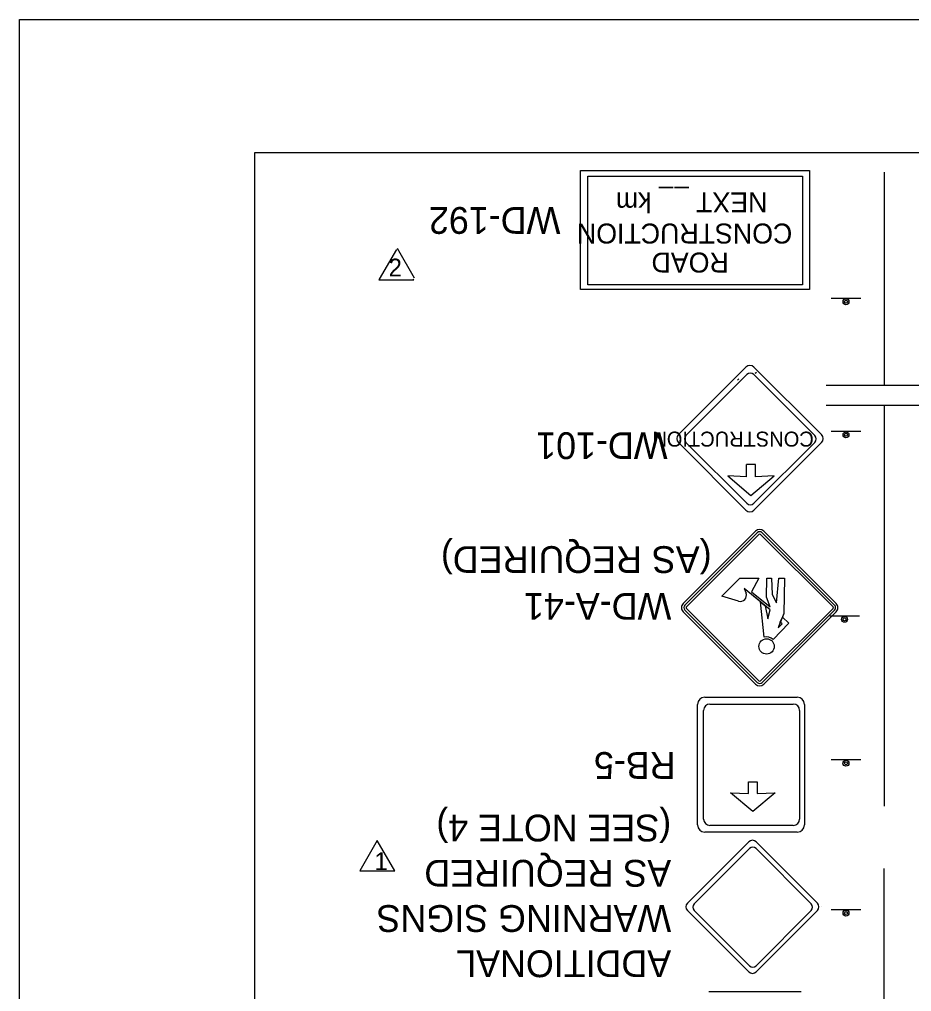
# Model space of a CAD drawing. Extents: x 1372 to 1588, y 125 to 404.
# Drawn here: x 1372.1 to 1444.6, y 325 to 404 of the extents above; entities that cross this region are included whole.
import ezdxf

# ---------------------------------------------------------------- set-up
doc = ezdxf.new("R2010")
doc.units = 0
for name, color, linetype in [('Level 1', 7, 'Continuous'), ('Level 10', 7, 'Continuous'), ('Level 2', 7, 'Continuous'), ('Level 44', 7, 'Continuous'), ('Level 60', 7, 'Continuous'), ('Level 63', 7, 'Continuous')]:
    doc.layers.add(name, color=color, linetype=linetype)

msp = doc.modelspace()

# ---------------------------------------------------------------- linework, layer by layer
at = {"layer": 'Level 1'}
for p, q in [((1431.885, 362.391), (1425.997, 356.51)), ((1432.015, 362.26), (1426.128, 356.379)), ((1432.146, 362.129), (1426.259, 356.248)), ((1438.172, 356.244), (1432.287, 362.129)), ((1438.303, 356.375), (1432.419, 362.26)), ((1438.434, 356.507), (1432.55, 362.391)), ((1425.997, 355.845), (1431.881, 349.961)), ((1426.128, 355.976), (1432.011, 350.092)), ((1426.258, 356.107), (1432.142, 350.222)), ((1432.284, 350.222), (1438.172, 356.103)), ((1432.415, 350.091), (1438.303, 355.973)), ((1432.546, 349.96), (1438.433, 355.842)), ((1432.488, 352.538), (1432.503, 352.538))]:
    msp.add_line(p, q, dxfattribs=at)
for points in [[(1430.489, 356.695), (1429.138, 357.098), (1430.599, 358.574), (1432.137, 358.574), (1431.561, 357.461), (1433.053, 356.239), (1432.761, 357.018), (1432.799, 358.574), (1433.165, 358.574), (1433.232, 357.245), (1433.591, 356.566), (1433.779, 358.574), (1434.229, 358.574), (1434.168, 355.691), (1433.705, 354.533), (1434.031, 354.867)], [(1430.489, 356.695), (1429.138, 357.098), (1430.599, 358.574), (1432.137, 358.574), (1431.561, 357.461), (1433.053, 356.239), (1432.761, 357.018), (1432.799, 358.574), (1433.165, 358.574), (1433.232, 357.245), (1433.591, 356.566), (1433.779, 358.574), (1434.229, 358.574), (1434.168, 355.691), (1433.705, 354.533), (1434.031, 354.867)], [(1430.489, 356.695), (1429.138, 357.098), (1430.599, 358.574), (1432.137, 358.574), (1431.561, 357.461), (1433.053, 356.239), (1432.761, 357.018), (1432.799, 358.574), (1433.165, 358.574), (1433.232, 357.245), (1433.591, 356.566)], [(1433.591, 356.566), (1433.779, 358.574), (1434.229, 358.574), (1434.168, 355.691), (1434.057, 355.413), (1434.591, 354.908), (1433.308, 353.583)], [(1432.572, 353.772), (1432.274, 356.642), (1432.657, 356.326), (1432.875, 355.256), (1433.052, 356.001), (1430.956, 357.731), (1431.101, 357.357)], [(1432.572, 353.772), (1432.274, 356.642), (1432.657, 356.326), (1432.875, 355.256), (1433.052, 356.001), (1430.956, 357.731), (1431.101, 357.357)], [(1432.572, 353.772), (1432.274, 356.643), (1430.956, 357.731), (1431.101, 357.357)], [(1434.031, 354.867), (1433.888, 354.988), (1434.058, 355.412), (1434.591, 354.908), (1433.308, 353.583)], [(1434.031, 354.867), (1433.888, 354.988), (1434.058, 355.412), (1434.591, 354.908), (1433.308, 353.583)]]:
    msp.add_lwpolyline(points, dxfattribs=at)
for points in [[(1432.657, 356.328), (1432.875, 355.256), (1433.052, 356.001)], [(1434.031, 354.867), (1433.887, 354.988), (1433.705, 354.533)], [(1401.132, 337.257), (1399.713, 334.787), (1402.551, 334.787)]]:
    msp.add_lwpolyline(points, close=True, dxfattribs=at)
msp.add_circle((1432.773, 353.023), 0.624, dxfattribs=at)
msp.add_circle((1432.773, 353.023), 0.624, dxfattribs=at)
msp.add_circle((1432.773, 353.023), 0.624, dxfattribs=at)
for centre, radius, start, end in [((1432.217, 362.058), 0.471, 45, 134.96517), ((1432.217, 362.058), 0.285, 45, 134.96517), ((1432.217, 362.058), 0.1, 45, 134.96517), ((1430.633, 357.176), 0.502, 253.38102, 21.09993), ((1430.633, 357.176), 0.502, 253.38102, 21.09993), ((1430.633, 357.176), 0.502, 253.38102, 21.09993), ((1426.329, 356.178), 0.471, 134.96511, 225), ((1426.329, 356.178), 0.285, 134.96511, 225), ((1438.101, 356.174), 0.285, 314.965, 45), ((1438.101, 356.174), 0.471, 314.965, 45), ((1426.329, 356.178), 0.1, 134.96511, 225), ((1438.101, 356.174), 0.1, 314.965, 45), ((1432.773, 353.023), 0.775, 46.3135, 104.9576), ((1432.773, 353.023), 0.775, 46.3135, 104.9576), ((1432.773, 353.023), 0.775, 46.3135, 104.9576), ((1432.214, 350.294), 0.285, 225, 314.96508), ((1432.214, 350.294), 0.1, 225, 314.96508), ((1432.214, 350.294), 0.471, 225, 314.96508)]:
    msp.add_arc(centre, radius, start, end, dxfattribs=at)
at = {"layer": 'Level 10'}
for p, q in [((1442.325, 391.558), (1442.325, 374.244)), ((1442.325, 372.627), (1442.325, 340.053)), ((1442.325, 157.871), (1442.325, 334.977))]:
    msp.add_line(p, q, dxfattribs=at)
at = {"layer": 'Level 2'}
for p, q in [((1431.859, 375.22), (1431.963, 375.324)), ((1430.401, 374.653), (1430.505, 374.757))]:
    msp.add_line(p, q, dxfattribs=at)
for points in [[(1436.268, 382.037), (1417.645, 382.037), (1417.645, 391.696), (1436.268, 391.696)], [(1435.684, 382.418), (1418.259, 382.418), (1418.259, 391.227), (1435.684, 391.227)]]:
    msp.add_lwpolyline(points, close=True, dxfattribs=at)
at = {"layer": 'Level 44'}
for p, q in [((1440.44, 381.307), (1438.022, 381.307)), ((1431.094, 375.728), (1425.609, 370.237)), ((1437.237, 370.237), (1431.743, 375.728)), ((1426.221, 370.177), (1431.159, 375.118)), ((1431.743, 375.118), (1436.686, 370.177)), ((1437.623, 374.244), (1454.713, 374.244)), ((1437.623, 372.627), (1454.803, 372.627)), ((1437.232, 370.237), (1437.237, 370.237)), ((1440.44, 370.493), (1438.021, 370.493)), ((1425.609, 369.586), (1431.094, 364.101)), ((1431.159, 364.654), (1426.221, 369.591)), ((1436.686, 369.591), (1431.743, 364.654)), ((1431.743, 364.101), (1437.237, 369.586)), ((1431.123, 367.819), (1431.123, 366.811)), ((1431.88, 367.819), (1431.128, 367.819)), ((1431.88, 366.811), (1431.88, 367.819)), ((1431.123, 366.811), (1429.614, 366.892)), ((1429.614, 366.892), (1431.501, 365.301)), ((1431.501, 365.301), (1433.389, 366.892)), ((1433.389, 366.892), (1431.88, 366.811)), ((1438.017, 355.579), (1438.017, 355.579)), ((1440.323, 355.493), (1437.903, 355.493)), ((1427.747, 348.894), (1435.265, 348.894)), ((1427.166, 338.512), (1427.166, 348.311)), ((1427.647, 338.995), (1427.647, 347.815)), ((1428.17, 348.338), (1434.936, 348.338)), ((1435.457, 347.817), (1435.457, 347.815)), ((1435.457, 347.815), (1435.457, 338.995)), ((1435.844, 348.314), (1435.844, 348.311)), ((1435.844, 348.311), (1435.844, 338.512)), ((1440.44, 343.8), (1438.021, 343.8)), ((1434.936, 338.473), (1428.17, 338.473)), ((1435.265, 337.932), (1427.747, 337.932)), ((1431.324, 337.147), (1426.337, 332.155)), ((1426.895, 332.1), (1431.384, 336.592)), ((1436.908, 332.155), (1431.914, 337.147)), ((1431.914, 336.592), (1436.409, 332.1)), ((1436.905, 332.155), (1436.908, 332.155)), ((1437.206, 331.855), (1437.206, 331.855)), ((1426.337, 331.562), (1431.324, 326.576)), ((1431.384, 327.078), (1426.895, 331.566)), ((1436.409, 331.566), (1431.914, 327.078)), ((1431.914, 326.576), (1436.908, 331.562)), ((1440.44, 331.622), (1438.02, 331.622)), ((1428.08, 324.976), (1435.596, 324.976)), ((1428.102, 324.975), (1435.597, 324.975)), ((1428.102, 324.975), (1435.597, 324.975))]:
    msp.add_line(p, q, dxfattribs=at)
msp.add_lwpolyline([(1433.471, 341.136), (1431.656, 339.608), (1429.841, 341.136), (1431.293, 341.059), (1431.293, 342.027), (1432.019, 342.027), (1432.019, 341.059)], close=True, dxfattribs=at)
for centre, radius in [((1439.226, 381.035), 0.242), ((1439.226, 381.035), 0.121), ((1439.226, 370.222), 0.242), ((1439.226, 370.222), 0.121), ((1439.108, 355.223), 0.242), ((1439.108, 355.223), 0.121), ((1439.225, 343.529), 0.242), ((1439.225, 343.529), 0.121), ((1439.226, 331.351), 0.242), ((1439.226, 331.351), 0.121)]:
    msp.add_circle(centre, radius, dxfattribs=at)
for centre, radius, start, end in [((1431.42, 375.401), 0.459, 45, 135), ((1431.452, 374.824), 0.413, 45, 135), ((1425.931, 369.912), 0.459, 135, 225), ((1426.513, 369.884), 0.413, 135, 225), ((1436.392, 369.884), 0.413, 315, 44.99999), ((1436.908, 369.912), 0.459, 315, 44.99999), ((1431.452, 364.945), 0.413, 225, 315), ((1431.42, 364.424), 0.459, 225, 315), ((1427.747, 348.313), 0.58, 90, 179.99999), ((1435.264, 348.313), 0.58, 360, 89.99999), ((1428.17, 347.817), 0.522, 90, 179.99999), ((1434.935, 347.817), 0.522, 360, 89.99999), ((1428.17, 338.997), 0.522, 179.99999, 269.99999), ((1434.935, 338.997), 0.522, 270, 359.99999), ((1427.747, 338.513), 0.58, 179.99999, 269.99999), ((1435.264, 338.513), 0.58, 270, 359.99999), ((1431.621, 336.849), 0.418, 45, 135), ((1431.65, 336.324), 0.376, 45, 135), ((1426.631, 331.859), 0.418, 135, 225), ((1427.16, 331.834), 0.376, 135, 225), ((1436.141, 331.834), 0.376, 315, 44.99999), ((1436.61, 331.859), 0.418, 315, 44.99999), ((1431.65, 327.343), 0.376, 225, 315), ((1431.621, 326.87), 0.418, 225, 315)]:
    msp.add_arc(centre, radius, start, end, dxfattribs=at)
at = {"layer": 'Level 60'}
msp.add_line((1372.057, 403.977), (1372.057, 403.977), dxfattribs=at)
for points in [[(1372.057, 403.977), (1588.057, 403.977), (1588.057, 124.977), (1372.057, 124.977)], [(1391.183, 393.168), (1578.057, 393.168), (1578.057, 135.786), (1391.183, 135.786)]]:
    msp.add_lwpolyline(points, close=True, dxfattribs=at)
at = {"layer": 'Level 63'}
for points in [[(1402.687, 385.29), (1401.294, 382.865)], [(1404.169, 382.942), (1402.775, 385.367)], [(1401.294, 382.865), (1401.268, 382.82), (1404.107, 382.82), (1404.081, 382.865)]]:
    msp.add_lwpolyline(points, dxfattribs=at)

# ---------------------------------------------------------------- texts
at = {"layer": 'Level 1'}
msp.add_text('1', height=1.448, rotation=360, dxfattribs=at).set_placement((1400.905, 334.844))
at = {"layer": 'Level 10'}
for s, height, p in [('WD-192', 2.177, (1416.018, 388.73)), ('WD-101', 2.1774, (1424.73, 370.426)), ('(AS REQUIRED)', 2.177, (1428.306, 361.17)), ('WD-A-41', 2.1774, (1425.036, 357.364)), ('RB-5', 2.1774, (1425.376, 344.435)), ('(SEE NOTE 4)', 2.17698, (1425.021, 339.353)), ('AS REQUIRED', 2.17698, (1425.021, 335.676)), ('WARNING SIGNS', 2.17698, (1425.021, 331.999)), ('ADDITIONAL', 2.177, (1425.021, 328.322))]:
    msp.add_text(s, height=height, rotation=180, dxfattribs=at).set_placement(p)
at = {"layer": 'Level 44'}
for s, height, rotation, p in [('NEXT __ km', 1.625, 180, (1432.838, 389.925)), ('CONSTRUCTION', 1.625, 179.99999, (1434.864, 387.392)), ('ROAD', 1.625, 179.99999, (1429.702, 385.033)), ('2', 1.448, 360, (1402.06, 383.089)), ('CONSTRUCTION', 1.21784, 180, (1436.608, 370.48))]:
    msp.add_text(s, height=height, rotation=rotation, dxfattribs=at).set_placement(p)

doc.saveas('drawing.dxf')
